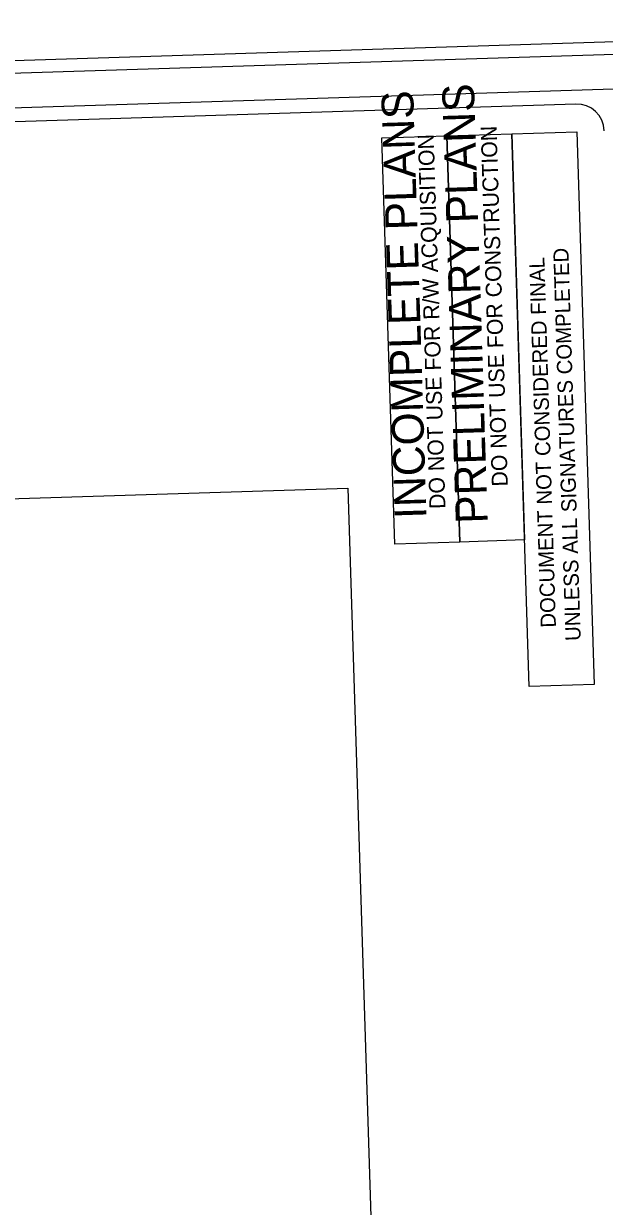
# Model space of a CAD drawing. Extents: x 2308163 to 2335412, y -96774 to 127732.
# Drawn here: x 2326787 to 2327102, y 124471 to 125112 of the extents above; entities that cross this region are included whole.
import ezdxf

# ---------------------------------------------------------------- set-up
doc = ezdxf.new("R2010")
doc.units = 0
for name, color, linetype in [('Sheet Plan Layout CELL', 7, 'Continuous'), ('Sheet Plot Border Inside CELL', 7, 'Continuous'), ('Sheet Plot Border Outside CELL', 7, 'Continuous'), ('Sheet Sticker Exception Certification CELL', 7, 'Continuous'), ('Sheet Sticker Incomplete CELL', 7, 'Continuous'), ('Sheet Sticker Preliminary CELL', 7, 'Continuous'), ('Sheet Title CELL', 7, 'Continuous')]:
    doc.layers.add(name, color=color, linetype=linetype)

msp = doc.modelspace()

# ---------------------------------------------------------------- linework, layer by layer
at = {"layer": 'Sheet Plan Layout CELL'}
msp.add_lwpolyline([(2326360.15, 123511.38), (2326318.28, 124840.01), (2326963.2, 124860.33), (2327005.07, 123531.7)], close=True, dxfattribs=at)
at = {"layer": 'Sheet Plot Border Inside CELL'}
msp.add_lwpolyline([(2327468.5, 122605.97), (2327389.78, 125104.48), (2325807.91, 125054.63), (2325886.64, 122556.12)], close=True, dxfattribs=at)
at = {"layer": 'Sheet Plot Border Outside CELL'}
msp.add_lwpolyline([(2325774.04, 125060.32), (2325853.59, 122535.57), (2327502.76, 122587.54), (2327423.2, 125112.28)], close=True, dxfattribs=at)
at = {"layer": 'Sheet Sticker Exception Certification CELL'}
for p, q in [((2327061.6, 124752.66), (2327052.15, 125052.57)), ((2327052.17, 125052.57), (2327087.4, 125053.68)), ((2327087.38, 125053.68), (2327096.83, 124753.77)), ((2327096.83, 124753.77), (2327061.6, 124752.66))]:
    msp.add_line(p, q, dxfattribs=at)
at = {"layer": 'Sheet Sticker Incomplete CELL'}
msp.add_lwpolyline([(2327023.86, 124831.07), (2326988.63, 124829.96), (2326981.68, 125050.35), (2327016.92, 125051.46)], close=True, dxfattribs=at)
at = {"layer": 'Sheet Sticker Preliminary CELL'}
msp.add_lwpolyline([(2327059.09, 124832.18), (2327023.86, 124831.07), (2327016.92, 125051.46), (2327052.15, 125052.57)], close=True, dxfattribs=at)
at = {"layer": 'Sheet Title CELL'}
for points in [[(2327371.53, 125085.14), (2325827.32, 125036.48)], [(2327086.93, 125068.67), (2325835.03, 125029.22)]]:
    msp.add_lwpolyline(points, dxfattribs=at)
msp.add_arc((2327087.31, 125053.68), 15, 1.80479, 91.80479, dxfattribs=at)

# ---------------------------------------------------------------- texts
at = {"layer": 'Sheet Sticker Exception Certification CELL'}
for s, p in [('UNLESS ALL SIGNATURES COMPLETED', (2327089.55, 124777.55)), ('DOCUMENT NOT CONSIDERED FINAL', (2327076.11, 124784.74))]:
    msp.add_text(s, height=8.25, rotation=91.80479, dxfattribs=at).set_placement(p)
at = {"layer": 'Sheet Sticker Incomplete CELL'}
for s, height, p in [('INCOMPLETE PLANS', 17.28, (2327005.9, 124843.93)), ('DO NOT USE FOR R/W ACQUISITION', 8.64, (2327016.16, 124849.13))]:
    msp.add_text(s, height=height, rotation=91.80479, dxfattribs=at).set_placement(p)
at = {"layer": 'Sheet Sticker Preliminary CELL'}
for s, height, p in [('PRELIMINARY PLANS', 17.28, (2327039.07, 124841.3)), ('DO NOT USE FOR CONSTRUCTION', 8.64, (2327050, 124861.31))]:
    msp.add_text(s, height=height, rotation=91.80479, dxfattribs=at).set_placement(p)

doc.saveas('drawing.dxf')
